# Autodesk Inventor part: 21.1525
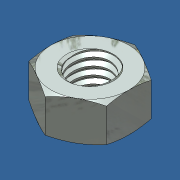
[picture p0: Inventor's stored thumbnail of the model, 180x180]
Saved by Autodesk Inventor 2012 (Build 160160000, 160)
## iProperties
Created: 2012-02
Part Number: 21.1525
Document SubType Name: Modeling
Designer: Administrator
Density: 7.85 g/cm^3
Material: Steel
Mass: 2.42169 g
Surface Area: 4.15922 cm^2
Volume: 0.308495 cm^3
Description: M6 HEX NUT
Translation Standard: STEP AP203
FileName: 90591A151.step
PreProcessor: SolidWorks 2007
PostProcessor: Build: 236a, Release: 2009 RTM - Date: Fri 02/22/2008
Sent Units: MM
Uncertainty: 1e-05
Author: Administrator
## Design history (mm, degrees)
feature "Base1"
body "Solid1"
